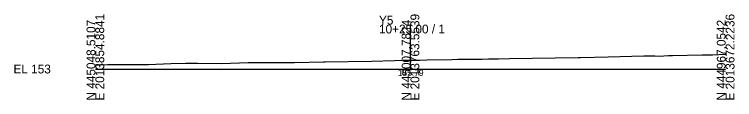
# Model space of a CAD drawing. Extents: x -26 to 203, y -10 to 4517.
# Drawn here: x -25.7 to 202.8, y 490.3 to 517.3 of the extents above; entities that cross this region are included whole.
import ezdxf

# ---------------------------------------------------------------- set-up
doc = ezdxf.new("R2010")
doc.units = 0
for name, color, linetype in [('Default', 7, 'Continuous'), ('Exist Cross Section Cell', 7, 'Continuous'), ('Exist XS Center Line Elevation Label', 7, 'Continuous'), ('Exist XS Ground Line', 7, 'Continuous')]:
    doc.layers.add(name, color=color, linetype=linetype)

msp = doc.modelspace()

# ---------------------------------------------------------------- linework, layer by layer
at = {"layer": 'Exist Cross Section Cell'}
for p, q in [((100, 500), (100, 514.08)), ((0, 500), (100, 500)), ((100, 500), (200, 500))]:
    msp.add_line(p, q, dxfattribs=at)
at = {"layer": 'Exist XS Ground Line'}
msp.add_lwpolyline([(0, 501.35), (1.04, 501.37), (3.85, 501.4), (8.37, 501.41), (16.89, 501.46), (23.95, 501.73), (28.64, 501.88), (32.41, 501.88), (40.16, 501.76), (48.51, 502.06), (50.54, 502.11), (52.18, 502.12), (63.19, 502.08), (72.37, 502.26), (72.87, 502.26), (87.63, 502.51), (94.9, 502.75), (97.62, 502.78), (100, 502.79), (102.93, 502.8), (105.29, 502.88), (113.16, 503.05), (115.04, 503.1), (120.3, 503.14), (121.42, 503.15), (122.7, 503.15), (124.7, 503.2), (127.45, 503.23), (127.93, 503.23), (131.46, 503.29), (153.16, 503.66), (153.97, 503.68), (162.77, 503.83), (174.08, 504.16), (177.52, 504.14), (178.92, 504.1), (181.89, 504.25), (183.11, 504.33), (192.6, 504.48), (193.81, 504.49), (195.84, 504.55), (200, 504.69)], dxfattribs=at)

# ---------------------------------------------------------------- texts
at = {"layer": 'Default'}
msp.add_text('-', height=0.0001, dxfattribs=at).set_placement((0, 500))
at = {"layer": 'Exist Cross Section Cell'}
for s, p in [('E 2013854.8841', (2.8, 490)), ('E 2013763.5539', (102.8, 490)), ('E 2013672.2236', (202.8, 490)), ('N 445048.5107', (0, 490)), ('N 445007.7824', (100, 490)), ('N 444967.0542', (200, 490))]:
    msp.add_text(s, height=2.8, rotation=90, dxfattribs=at).set_placement(p)
for s, p in [('Y5', (90, 514.08)), ('10+25.00 / 1', (90, 511.28)), ('EL 153', (-26, 498.6))]:
    msp.add_text(s, height=2.8, dxfattribs=at).set_placement(p)
at = {"layer": 'Exist XS Center Line Elevation Label'}
msp.add_text('155.79', height=2, dxfattribs=at).set_placement((95.97, 497.79))

doc.saveas('drawing.dxf')
